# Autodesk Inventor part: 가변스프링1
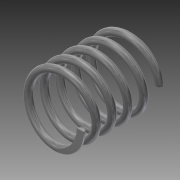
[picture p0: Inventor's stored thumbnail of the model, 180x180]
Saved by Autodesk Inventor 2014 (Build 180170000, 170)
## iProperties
Created: 2016-02
Part Number: 가변스프링1
Material: 스테인레스 스틸
Document SubType Name: Modeling
Designer: Owner
Density: 8.08 g/cm^3
Appearance: 반연마
Mass: 6.65473 g
Surface Area: 16.7342 cm^2
Volume: 0.823605 cm^3
Author: Owner
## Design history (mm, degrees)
sketch "스케치1"
  geometry: L1 (0, 0)-(8.5, 0); L2 (8.5, 0)-(8.5, 22.511); L3 (8.5, 22.511)-(0, 22.511); L4 (0, 22.511)-(0, 0); C1 r 1 at (8.5, 0)
  constraints: 8 end point, 2 parallel, 1 centre point, 1 coincident, 1 horizontal, 1 perpendicular
  dimensions: "d0" = 2 diameter of C1; "d1" = 17 diameter of L2 L4; "d2" = 22.51063 distance of L1.end L2.end (derived)
feature "코일1" sketch "스케치1" pitch "d3" = 10; turns "d5" = 5; dims "d4" = 22.51063 (= d2), "d6" = 0, angle "d7" = 90 deg, angle "d8" = 90 deg, "d9" = 0, "d10" = 0
sketch "스케치2"
  geometry: L1 (-9.5, 0)-(-7.5, 0) reference; 1 further point
  constraints: 1 horizontal alignment
extrude "돌출1" cut sketch "스케치2" distance "d11" = 10; taper "d12" = 0 deg
node "작업 평면1"
sketch "스케치3"
  geometry: L1 (1, 0)-(-1, 0) reference; 1 further point
  constraints: 1 horizontal alignment
extrude "돌출2" cut sketch "스케치3" distance "d13" = 10; taper "d14" = 0 deg
node "솔리드1"
node "절단 모서리 투영1"
node "절단 모서리 투영2"
